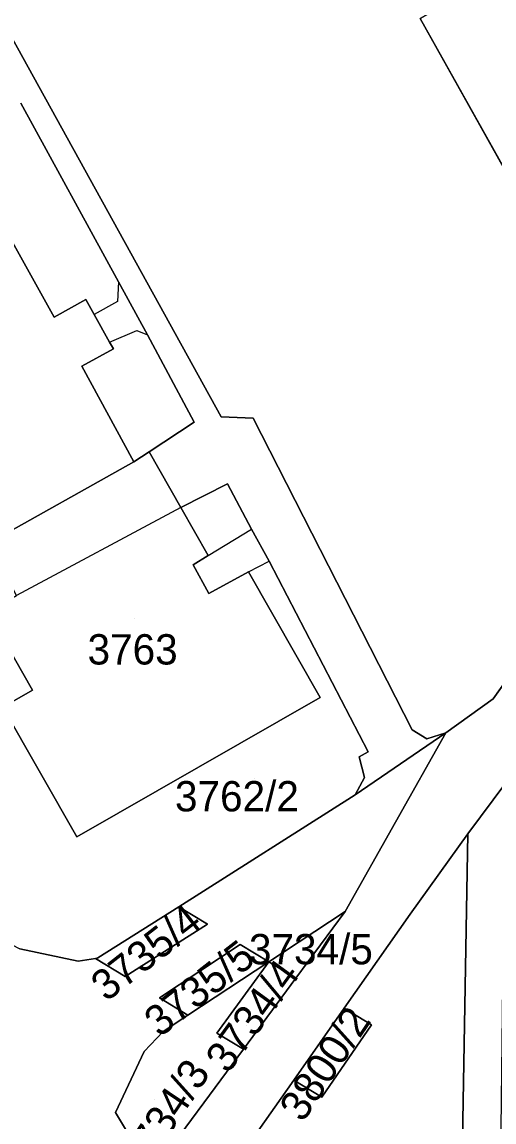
# Model space of a CAD drawing. Extents: x -262715 to -259381, y -1237238 to -1231182.
# Drawn here: x -261656.1 to -261625, y -1235504.5 to -1235432 of the extents above; entities that cross this region are included whole.
import ezdxf

# ---------------------------------------------------------------- set-up
doc = ezdxf.new("R2010")
doc.units = 0
for name, color, linetype in [('body_kn', 7, 'Continuous'), ('kladpar_druhypozemkov', 7, 'Continuous'), ('kladpar_hranice', 7, 'Continuous'), ('kladpar_parcelnecisla', 7, 'Continuous'), ('kladpar_plochy', 7, 'Continuous'), ('zappar_hrandruhpozemk', 7, 'Continuous')]:
    doc.layers.add(name, color=color, linetype=linetype)

msp = doc.modelspace()

# ---------------------------------------------------------------- linework, layer by layer
at = {"layer": 'body_kn'}
for p, q in [((-261649.76, -1235449.09), (-261649.76, -1235449.09)), ((-261649.76, -1235449.09), (-261649.76, -1235449.09)), ((-261651.91, -1235450.26), (-261651.91, -1235450.26)), ((-261649.82, -1235450.39), (-261649.82, -1235450.39)), ((-261653.99, -1235451.42), (-261653.99, -1235451.42)), ((-261651.36, -1235451.24), (-261651.36, -1235451.24)), ((-261648.55, -1235452.3), (-261648.55, -1235452.3)), ((-261647.84, -1235452.59), (-261647.84, -1235452.59)), ((-261650.34, -1235453.07), (-261650.34, -1235453.07)), ((-261650.34, -1235453.07), (-261650.34, -1235453.07)), ((-261650.09, -1235453.51), (-261650.09, -1235453.51)), ((-261652.17, -1235454.67), (-261652.17, -1235454.67)), ((-261644.75, -1235458.36), (-261644.75, -1235458.36)), ((-261642.97, -1235458.01), (-261642.97, -1235458.01)), ((-261640.86, -1235458.1), (-261640.86, -1235458.1)), ((-261647.72, -1235460.3), (-261647.72, -1235460.3)), ((-261647.72, -1235460.3), (-261647.72, -1235460.3)), ((-261648.74, -1235460.98), (-261648.74, -1235460.98)), ((-261642.57, -1235462.42), (-261642.57, -1235462.42)), ((-261642.57, -1235462.42), (-261642.57, -1235462.42)), ((-261645.63, -1235463.99), (-261645.63, -1235463.99)), ((-261645.63, -1235463.99), (-261645.63, -1235463.99)), ((-261640.97, -1235465.41), (-261640.97, -1235465.41)), ((-261643.84, -1235467.14), (-261643.84, -1235467.14)), ((-261643.84, -1235467.14), (-261643.84, -1235467.14)), ((-261644.82, -1235467.77), (-261644.82, -1235467.77)), ((-261639.8, -1235467.52), (-261639.8, -1235467.52)), ((-261641.18, -1235468.23), (-261641.18, -1235468.23)), ((-261641.18, -1235468.23), (-261641.18, -1235468.23)), ((-261643.8, -1235469.66), (-261643.8, -1235469.66)), ((-261655.43, -1235476.04), (-261655.43, -1235476.04)), ((-261636.44, -1235476.52), (-261636.44, -1235476.52)), ((-261625.03, -1235476.61), (-261625.03, -1235476.61)), ((-261630.36, -1235478.64), (-261630.36, -1235478.64)), ((-261629.4, -1235479.24), (-261629.4, -1235479.24)), ((-261628.14, -1235478.84), (-261628.14, -1235478.84)), ((-261633.28, -1235480.1), (-261633.28, -1235480.1)), ((-261633.87, -1235480.43), (-261633.87, -1235480.43)), ((-261633.52, -1235481.8), (-261633.52, -1235481.8)), ((-261634.14, -1235482.94), (-261634.14, -1235482.94)), ((-261652.5, -1235485.71), (-261652.5, -1235485.71)), ((-261626.7, -1235485.5), (-261626.7, -1235485.5)), ((-261645.78, -1235490.32), (-261645.78, -1235490.32)), ((-261645.78, -1235490.32), (-261645.78, -1235490.32)), ((-261634.8, -1235490.64), (-261634.8, -1235490.64)), ((-261630.5, -1235490.8), (-261630.5, -1235490.8)), ((-261630.5, -1235490.8), (-261630.5, -1235490.8)), ((-261643.88, -1235491.48), (-261643.88, -1235491.48)), ((-261641.72, -1235492.8), (-261641.72, -1235492.8)), ((-261652.41, -1235493.92), (-261652.41, -1235493.92)), ((-261651.28, -1235493.73), (-261651.28, -1235493.73)), ((-261651.28, -1235493.73), (-261651.28, -1235493.73)), ((-261651.11, -1235493.7), (-261651.11, -1235493.7)), ((-261651.11, -1235493.7), (-261651.11, -1235493.7)), ((-261639.83, -1235493.96), (-261639.83, -1235493.96)), ((-261639.83, -1235493.96), (-261639.83, -1235493.96)), ((-261649.32, -1235494.93), (-261649.32, -1235494.93)), ((-261638.05, -1235495.04), (-261638.05, -1235495.04)), ((-261638.05, -1235495.04), (-261638.05, -1235495.04)), ((-261647.05, -1235496.32), (-261647.05, -1235496.32)), ((-261645.17, -1235497.48), (-261645.17, -1235497.48)), ((-261645.17, -1235497.48), (-261645.17, -1235497.48)), ((-261634.85, -1235497), (-261634.85, -1235497)), ((-261633.05, -1235498.1), (-261633.05, -1235498.1)), ((-261646.8, -1235498.55), (-261646.8, -1235498.55)), ((-261643.26, -1235498.65), (-261643.26, -1235498.65)), ((-261641.51, -1235499.72), (-261641.51, -1235499.72)), ((-261648.05, -1235499.86), (-261648.05, -1235499.86)), ((-261638.19, -1235501.76), (-261638.19, -1235501.76)), ((-261638.19, -1235501.76), (-261638.19, -1235501.76)), ((-261636.34, -1235502.89), (-261636.34, -1235502.89)), ((-261649.96, -1235503.9), (-261649.96, -1235503.9))]:
    msp.add_line(p, q, dxfattribs=at)
at = {"layer": 'kladpar_druhypozemkov'}
for p, q in [((-261648.67, -1235471.29), (-261648.67, -1235471.29)), ((-261640.75, -1235481.86), (-261640.75, -1235481.86)), ((-261647.83, -1235492.55), (-261647.83, -1235492.55)), ((-261637.14, -1235492.82), (-261637.14, -1235492.82)), ((-261643.95, -1235495.26), (-261643.95, -1235495.26)), ((-261641.31, -1235498.13), (-261641.31, -1235498.13)), ((-261635.91, -1235500.15), (-261635.91, -1235500.15)), ((-261647.41, -1235503.06), (-261647.41, -1235503.06))]:
    msp.add_line(p, q, dxfattribs=at)
at = {"layer": 'kladpar_hranice'}
for p, q in [((-261651.11, -1235493.7), (-261645.78, -1235490.32)), ((-261651.28, -1235493.73), (-261651.11, -1235493.7)), ((-261639.83, -1235493.96), (-261645.17, -1235497.48))]:
    msp.add_line(p, q, dxfattribs=at)
for points in [[(-261622.45, -1235472.98), (-261625.03, -1235476.61), (-261628.14, -1235478.84), (-261629.4, -1235479.24), (-261630.36, -1235478.64), (-261640.86, -1235458.1), (-261642.97, -1235458.01), (-261657.24, -1235432.19), (-261682.17, -1235386.46), (-261704.58, -1235346.36)], [(-261618.58, -1235425.29), (-261611.05, -1235439.15), (-261622.16, -1235445.45), (-261629.84, -1235431.72), (-261618.58, -1235425.29)], [(-261611.05, -1235439.15), (-261618.58, -1235425.29), (-261629.84, -1235431.72), (-261622.16, -1235445.45), (-261611.05, -1235439.15)], [(-261657.24, -1235432.19), (-261642.97, -1235458.01), (-261640.86, -1235458.1), (-261630.36, -1235478.64), (-261629.4, -1235479.24), (-261628.14, -1235478.84), (-261634.14, -1235482.94), (-261633.52, -1235481.8), (-261633.87, -1235480.43), (-261633.28, -1235480.1), (-261639.8, -1235467.52), (-261640.97, -1235465.41), (-261642.57, -1235462.42), (-261645.63, -1235463.99), (-261647.72, -1235460.3), (-261644.75, -1235458.36), (-261647.84, -1235452.59), (-261649.76, -1235449.09), (-261656.21, -1235437.32)], [(-261656.21, -1235437.32), (-261649.76, -1235449.09), (-261647.84, -1235452.59), (-261644.75, -1235458.36), (-261647.72, -1235460.3), (-261648.74, -1235460.98), (-261652.17, -1235454.67), (-261650.09, -1235453.51), (-261650.34, -1235453.07), (-261651.36, -1235451.24), (-261651.91, -1235450.26), (-261653.99, -1235451.42), (-261657.31, -1235445.48)], [(-261645.17, -1235497.48), (-261646.8, -1235498.55), (-261648.05, -1235499.86), (-261649.96, -1235503.9), (-261647.56, -1235507.9), (-261654.44, -1235511.45), (-261656.4, -1235506.74), (-261659.56, -1235500.5), (-261663.24, -1235496.16), (-261665.04, -1235494.76), (-261670.11, -1235493.07), (-261675.25, -1235493.34), (-261683.78, -1235497.41), (-261690.34, -1235499.06), (-261695.67, -1235499.03), (-261703.98, -1235497.19), (-261706.77, -1235495.17), (-261709.85, -1235490.75), (-261723.96, -1235463.86), (-261735.63, -1235441.97)], [(-261657.31, -1235445.48), (-261653.99, -1235451.42), (-261651.91, -1235450.26), (-261651.36, -1235451.24), (-261650.34, -1235453.07), (-261650.09, -1235453.51), (-261652.17, -1235454.67), (-261648.74, -1235460.98), (-261658.33, -1235466.33)], [(-261659.4, -1235525.07), (-261656.04, -1235521.99), (-261653.08, -1235518.57), (-261653.75, -1235515.64), (-261654.44, -1235511.45), (-261647.56, -1235507.9), (-261641.51, -1235499.72), (-261638.05, -1235495.04), (-261634.8, -1235490.64), (-261628.14, -1235478.84), (-261625.03, -1235476.61), (-261622.45, -1235472.98), (-261619.63, -1235469.01), (-261615.2, -1235462.78), (-261600.58, -1235454.79), (-261599.2, -1235458.61), (-261606.13, -1235462.18), (-261611.77, -1235465.09), (-261612.89, -1235465.94), (-261613.47, -1235466.73), (-261613.95, -1235467.38), (-261624.18, -1235482.14), (-261626.7, -1235485.5), (-261630.5, -1235490.8)], [(-261647.72, -1235460.3), (-261645.63, -1235463.99), (-261643.84, -1235467.14), (-261644.82, -1235467.77), (-261643.8, -1235469.66), (-261641.18, -1235468.23), (-261636.44, -1235476.52), (-261652.5, -1235485.71), (-261657.39, -1235477.16), (-261655.43, -1235476.04), (-261658.39, -1235470.88), (-261656.48, -1235469.79), (-261658.33, -1235466.33), (-261648.74, -1235460.98), (-261647.72, -1235460.3)], [(-261658.39, -1235470.88), (-261655.43, -1235476.04), (-261657.39, -1235477.16), (-261652.5, -1235485.71), (-261636.44, -1235476.52), (-261641.18, -1235468.23), (-261643.8, -1235469.66), (-261644.82, -1235467.77), (-261643.84, -1235467.14), (-261645.63, -1235463.99), (-261642.57, -1235462.42)], [(-261642.57, -1235462.42), (-261640.97, -1235465.41), (-261639.8, -1235467.52), (-261633.28, -1235480.1), (-261633.87, -1235480.43), (-261633.52, -1235481.8), (-261634.14, -1235482.94), (-261645.78, -1235490.32), (-261651.11, -1235493.7), (-261651.28, -1235493.73), (-261652.41, -1235493.92), (-261656.26, -1235493.1)], [(-261645.78, -1235490.32), (-261634.14, -1235482.94), (-261628.14, -1235478.84), (-261634.8, -1235490.64), (-261639.83, -1235493.96)], [(-261627.04, -1235505.68), (-261626.7, -1235485.5), (-261624.18, -1235482.14)], [(-261642.37, -1235511.43), (-261643.3, -1235509.03), (-261638.19, -1235501.76), (-261636.34, -1235502.89), (-261633.05, -1235498.1), (-261634.85, -1235497), (-261630.5, -1235490.8), (-261626.7, -1235485.5), (-261627.04, -1235505.68), (-261626.15, -1235505.78), (-261626.16, -1235509.14), (-261626.56, -1235509.76), (-261627.6, -1235510.25), (-261640.34, -1235512.21), (-261642.37, -1235511.43)], [(-261662.36, -1235486.93), (-261661.1, -1235489.22), (-261659.04, -1235491.67), (-261656.26, -1235493.1), (-261652.41, -1235493.92), (-261651.28, -1235493.73)], [(-261645.78, -1235490.32), (-261643.88, -1235491.48), (-261649.32, -1235494.93), (-261651.28, -1235493.73)], [(-261651.28, -1235493.73), (-261649.32, -1235494.93), (-261643.88, -1235491.48), (-261645.78, -1235490.32)], [(-261630.5, -1235490.8), (-261634.85, -1235497), (-261638.19, -1235501.76), (-261643.3, -1235509.03), (-261644.66, -1235515.8), (-261648.29, -1235518.77), (-261651.44, -1235521.4), (-261655.59, -1235526.78), (-261670.52, -1235538.34), (-261682.99, -1235546.77), (-261696.33, -1235555.5), (-261705.24, -1235561.83), (-261708.58, -1235565.06), (-261712.83, -1235570.45), (-261714.55, -1235575.78), (-261715.32, -1235579.16), (-261716.25, -1235584.42), (-261716.6, -1235604.44), (-261716.66, -1235608.5), (-261716.9, -1235617.19), (-261717.12, -1235627), (-261717.4, -1235648.09)], [(-261639.83, -1235493.96), (-261634.8, -1235490.64), (-261638.05, -1235495.04), (-261639.83, -1235493.96)], [(-261645.17, -1235497.48), (-261647.05, -1235496.32), (-261641.72, -1235492.8), (-261639.83, -1235493.96)], [(-261639.83, -1235493.96), (-261641.72, -1235492.8), (-261647.05, -1235496.32), (-261645.17, -1235497.48)], [(-261647.56, -1235507.9), (-261649.96, -1235503.9), (-261648.05, -1235499.86), (-261646.8, -1235498.55), (-261645.17, -1235497.48), (-261639.83, -1235493.96), (-261643.26, -1235498.65), (-261641.51, -1235499.72), (-261647.56, -1235507.9)], [(-261638.05, -1235495.04), (-261641.51, -1235499.72), (-261643.26, -1235498.65), (-261639.83, -1235493.96), (-261638.05, -1235495.04)], [(-261638.19, -1235501.76), (-261634.85, -1235497), (-261633.05, -1235498.1), (-261636.34, -1235502.89), (-261638.19, -1235501.76)]]:
    msp.add_lwpolyline(points, dxfattribs=at)
at = {"layer": 'kladpar_plochy'}
for p, q in [((-261642.97, -1235458.01), (-261657.24, -1235432.19)), ((-261629.84, -1235431.72), (-261622.16, -1235445.45)), ((-261640.86, -1235458.1), (-261642.97, -1235458.01)), ((-261630.36, -1235478.64), (-261640.86, -1235458.1)), ((-261622.45, -1235472.98), (-261625.03, -1235476.61)), ((-261625.03, -1235476.61), (-261628.14, -1235478.84)), ((-261629.4, -1235479.24), (-261630.36, -1235478.64)), ((-261628.14, -1235478.84), (-261629.4, -1235479.24))]:
    msp.add_line(p, q, dxfattribs=at)
for points in [[(-261618.58, -1235425.29), (-261611.05, -1235439.15), (-261622.16, -1235445.45), (-261629.84, -1235431.72)], [(-261647.72, -1235460.3), (-261645.63, -1235463.99), (-261643.84, -1235467.14), (-261644.82, -1235467.77), (-261643.8, -1235469.66), (-261641.18, -1235468.23), (-261636.44, -1235476.52), (-261652.5, -1235485.71), (-261657.39, -1235477.16), (-261655.43, -1235476.04), (-261658.39, -1235470.88), (-261656.48, -1235469.79), (-261658.33, -1235466.33), (-261648.74, -1235460.98)], [(-261642.37, -1235511.43), (-261643.3, -1235509.03), (-261638.19, -1235501.76), (-261636.34, -1235502.89), (-261633.05, -1235498.1), (-261634.85, -1235497), (-261630.5, -1235490.8), (-261626.7, -1235485.5), (-261627.04, -1235505.68), (-261626.15, -1235505.78), (-261626.16, -1235509.14), (-261626.56, -1235509.76), (-261627.6, -1235510.25), (-261640.34, -1235512.21)], [(-261651.11, -1235493.7), (-261645.78, -1235490.32), (-261643.88, -1235491.48), (-261649.32, -1235494.93), (-261651.28, -1235493.73)], [(-261639.83, -1235493.96), (-261634.8, -1235490.64), (-261638.05, -1235495.04)], [(-261639.83, -1235493.96), (-261645.17, -1235497.48), (-261647.05, -1235496.32), (-261641.72, -1235492.8)], [(-261647.56, -1235507.9), (-261649.96, -1235503.9), (-261648.05, -1235499.86), (-261646.8, -1235498.55), (-261645.17, -1235497.48), (-261639.83, -1235493.96), (-261643.26, -1235498.65), (-261641.51, -1235499.72)], [(-261638.05, -1235495.04), (-261641.51, -1235499.72), (-261643.26, -1235498.65), (-261639.83, -1235493.96)], [(-261638.19, -1235501.76), (-261634.85, -1235497), (-261633.05, -1235498.1), (-261636.34, -1235502.89)]]:
    msp.add_lwpolyline(points, close=True, dxfattribs=at)
for points in [[(-261657.24, -1235432.19), (-261642.97, -1235458.01), (-261640.86, -1235458.1), (-261630.36, -1235478.64), (-261629.4, -1235479.24), (-261628.14, -1235478.84), (-261634.14, -1235482.94), (-261633.52, -1235481.8), (-261633.87, -1235480.43), (-261633.28, -1235480.1), (-261639.8, -1235467.52), (-261640.97, -1235465.41), (-261642.57, -1235462.42), (-261645.63, -1235463.99), (-261647.72, -1235460.3), (-261644.75, -1235458.36), (-261647.84, -1235452.59), (-261649.76, -1235449.09), (-261656.21, -1235437.32)], [(-261656.21, -1235437.32), (-261649.76, -1235449.09), (-261647.84, -1235452.59), (-261644.75, -1235458.36), (-261647.72, -1235460.3), (-261648.74, -1235460.98), (-261652.17, -1235454.67), (-261650.09, -1235453.51), (-261650.34, -1235453.07), (-261651.36, -1235451.24), (-261651.91, -1235450.26), (-261653.99, -1235451.42), (-261657.31, -1235445.48)], [(-261657.31, -1235445.48), (-261653.99, -1235451.42), (-261651.91, -1235450.26), (-261651.36, -1235451.24), (-261650.34, -1235453.07), (-261650.09, -1235453.51), (-261652.17, -1235454.67), (-261648.74, -1235460.98), (-261658.33, -1235466.33)], [(-261647.56, -1235507.9), (-261641.51, -1235499.72), (-261638.05, -1235495.04), (-261634.8, -1235490.64), (-261628.14, -1235478.84), (-261625.03, -1235476.61), (-261622.45, -1235472.98), (-261619.63, -1235469.01), (-261615.2, -1235462.78), (-261600.58, -1235454.79), (-261599.2, -1235458.61), (-261606.13, -1235462.18), (-261611.77, -1235465.09), (-261612.89, -1235465.94), (-261613.47, -1235466.73), (-261613.95, -1235467.38), (-261624.18, -1235482.14), (-261626.7, -1235485.5), (-261630.5, -1235490.8), (-261634.85, -1235497), (-261638.19, -1235501.76), (-261643.3, -1235509.03)], [(-261658.39, -1235470.88), (-261655.43, -1235476.04), (-261657.39, -1235477.16), (-261652.5, -1235485.71), (-261636.44, -1235476.52), (-261641.18, -1235468.23), (-261643.8, -1235469.66), (-261644.82, -1235467.77), (-261643.84, -1235467.14), (-261645.63, -1235463.99), (-261642.57, -1235462.42), (-261640.97, -1235465.41), (-261639.8, -1235467.52), (-261633.28, -1235480.1), (-261633.87, -1235480.43), (-261633.52, -1235481.8), (-261634.14, -1235482.94), (-261645.78, -1235490.32), (-261651.11, -1235493.7), (-261651.28, -1235493.73), (-261652.41, -1235493.92), (-261656.26, -1235493.1)], [(-261656.26, -1235493.1), (-261652.41, -1235493.92), (-261651.28, -1235493.73), (-261649.32, -1235494.93), (-261643.88, -1235491.48), (-261645.78, -1235490.32), (-261634.14, -1235482.94), (-261628.14, -1235478.84), (-261634.8, -1235490.64), (-261639.83, -1235493.96), (-261641.72, -1235492.8), (-261647.05, -1235496.32), (-261645.17, -1235497.48), (-261646.8, -1235498.55), (-261648.05, -1235499.86), (-261649.96, -1235503.9), (-261647.56, -1235507.9), (-261654.44, -1235511.45), (-261656.4, -1235506.74)], [(-261627.04, -1235505.68), (-261626.7, -1235485.5), (-261624.18, -1235482.14), (-261624.21, -1235483.74), (-261613.27, -1235483.69), (-261613.28, -1235486.09), (-261624.29, -1235486.05), (-261624.56, -1235508.73)]]:
    msp.add_lwpolyline(points, dxfattribs=at)
at = {"layer": 'zappar_hrandruhpozemk'}
for p, q in [((-261649.76, -1235449.09), (-261649.82, -1235450.39)), ((-261649.82, -1235450.39), (-261651.36, -1235451.24)), ((-261650.34, -1235453.07), (-261648.55, -1235452.3)), ((-261648.55, -1235452.3), (-261647.84, -1235452.59)), ((-261645.63, -1235463.99), (-261656.48, -1235469.79)), ((-261643.84, -1235467.14), (-261640.97, -1235465.41)), ((-261641.18, -1235468.23), (-261639.8, -1235467.52))]:
    msp.add_line(p, q, dxfattribs=at)

# ---------------------------------------------------------------- texts
at = {"layer": 'kladpar_parcelnecisla'}
for s, p in [('3763', (-261651.797, -1235474.34)), ('3762/2', (-261646.028, -1235484.03)), ('3734/5', (-261641.143, -1235494.12))]:
    msp.add_text(s, height=2, dxfattribs=at).set_placement(p)
for s, rotation, p in [('3735/4', 38, (-261650.554, -1235496.635)), ('3735/5', 38, (-261647.037, -1235498.989)), ('3734/4', 54, (-261642.524, -1235501.399)), ('3800/2', 56, (-261637.592, -1235504.615)), ('3734/3', 56, (-261648.208, -1235508.065))]:
    msp.add_text(s, height=2, rotation=rotation, dxfattribs=at).set_placement(p)

doc.saveas('drawing.dxf')
